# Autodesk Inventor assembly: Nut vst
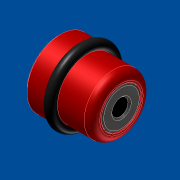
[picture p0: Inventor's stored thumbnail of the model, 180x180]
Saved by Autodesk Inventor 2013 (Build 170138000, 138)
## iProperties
Shininess: 20.0
Length Units: 11269
Angle Units: 11279
Time Units: 11290
Mass Units: 11283
Length Display Precision: 3
Angle Display Precision: 2
Created: 2001-04
Part Number: Nut vst
Document SubType Name: Baugruppe
Designer: dl
Density: 0.0
Volumn: 0.0
Area: 0.0
PropertySet Name: Model Information
Control State: 0
Master: False
Checked Out: False
Author: dl
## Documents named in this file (4)
- C:\Webworld\Webworld2014\ATC2013\Assemblies\ATC-Baby Carriage\3-FRONT WHEEL\Nut vst.iam
- C:\Webworld\Webworld2014\ATC2013\Assemblies\ATC-Baby Carriage\3-FRONT WHEEL\Nut.ipt
- C:\Webworld\Webworld2014\ATC2013\Assemblies\ATC-Baby Carriage\3-FRONT WHEEL\Locking_device.ipt
- C:\Webworld\Webworld2014\ATC2013\Assemblies\ATC-Baby Carriage\3-FRONT WHEEL\O-Ring.ipt
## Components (3 placed, 3 different names)
1. Nut:1 — Flush:1, Mate:1, Mate:2, Mate:3
2. Locking_device:1 — Flush:1, Mate:1
3. O-Ring:1 — Flush:2, Mate:2, Mate:3
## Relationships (5: Mate 3, Flush 2)
- Flush:1: Nut:1 ↔ Locking_device:1
- Mate:1: Nut:1 ↔ Locking_device:1
- Flush:2: O-Ring:1
- Mate:2: Nut:1 ↔ O-Ring:1
- Mate:3: Nut:1 ↔ O-Ring:1
